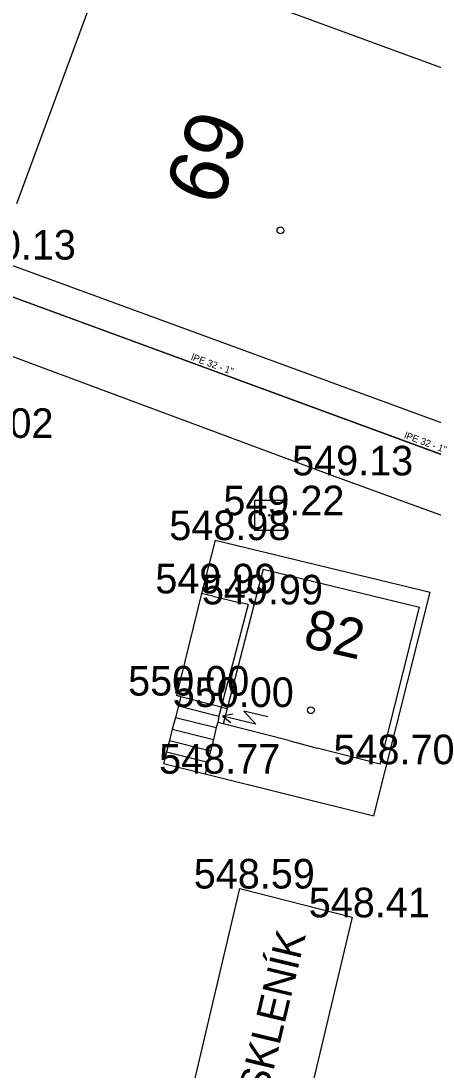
# Model space of a CAD drawing. Extents: x -669995 to -669686, y -1125551 to -1125263.
# Drawn here: x -669796.45 to -669786.01, y -1125325.67 to -1125299.08 of the extents above; entities that cross this region are included whole.
import ezdxf

# ---------------------------------------------------------------- set-up
doc = ezdxf.new("R2010")
doc.units = 0
for name, color, linetype in [('G_Bod_tecka', 7, 'Continuous'), ('G_Bod_vyska', 7, 'Continuous'), ('G_Budovy-znacky', 7, 'Continuous'), ('G_Budovy_Objekty', 7, 'Continuous'), ('G_Budovy_vstupy', 7, 'Continuous'), ('G_Cesty_Schody', 7, 'Continuous'), ('G_Cisla_jina', 7, 'Continuous'), ('G_Cisla_popisna', 7, 'Continuous'), ('G_Ploty', 7, 'Continuous'), ('G_Poznamky_odkaz', 7, 'Continuous'), ('G_Site-Rozvadece', 7, 'Continuous'), ('G_Site-Sachty_N', 7, 'Continuous'), ('G_Z_VODA_podz_kotovane', 7, 'Continuous'), ('Vrstva 25', 7, 'Continuous'), ('Vrstva 4', 7, 'Continuous')]:
    doc.layers.add(name, color=color, linetype=linetype)

msp = doc.modelspace()

# ---------------------------------------------------------------- linework, layer by layer
at = {"layer": 'G_Bod_tecka'}
for p, q in [((-669788.56, -1125310.6), (-669788.56, -1125310.6)), ((-669790.16, -1125311.61), (-669790.16, -1125311.61)), ((-669791.53, -1125312.24), (-669791.53, -1125312.24)), ((-669791.88, -1125313.59), (-669791.88, -1125313.59)), ((-669790.7, -1125313.87), (-669790.7, -1125313.87)), ((-669792.51, -1125316.18), (-669792.51, -1125316.18)), ((-669791.38, -1125316.47), (-669791.38, -1125316.47)), ((-669787.35, -1125317.92), (-669787.35, -1125317.92)), ((-669791.79, -1125318.16), (-669791.79, -1125318.16)), ((-669790.91, -1125321.07), (-669790.91, -1125321.07)), ((-669788.06, -1125321.8), (-669788.06, -1125321.8))]:
    msp.add_line(p, q, dxfattribs=at)
at = {"layer": 'G_Budovy-znacky'}
for centre in [(-669789.879, -1125304.39), (-669789.109, -1125316.551)]:
    msp.add_circle(centre, 0.0875, dxfattribs=at)
at = {"layer": 'G_Budovy_Objekty'}
for p, q in [((-669779.82, -1125302.48), (-669794.17, -1125297.19)), ((-669782.72, -1125310.4), (-669797.09, -1125305.13)), ((-669791.53, -1125312.24), (-669791.88, -1125313.59)), ((-669791.53, -1125312.24), (-669786.09, -1125313.56)), ((-669790.32, -1125312.98), (-669791.23, -1125316.51)), ((-669790.32, -1125312.98), (-669786.36, -1125313.94)), ((-669791.88, -1125313.59), (-669792.51, -1125316.18)), ((-669791.59, -1125313.66), (-669791.88, -1125313.59)), ((-669787.51, -1125319.23), (-669786.09, -1125313.56)), ((-669790.7, -1125313.87), (-669791.06, -1125315.26)), ((-669790.7, -1125313.87), (-669790.96, -1125313.81)), ((-669787.35, -1125317.92), (-669786.36, -1125313.94)), ((-669792.4, -1125316.21), (-669792.51, -1125316.18)), ((-669791.28, -1125316.08), (-669791.38, -1125316.47)), ((-669791.38, -1125316.47), (-669792.4, -1125316.21)), ((-669791.44, -1125316.7), (-669791.47, -1125316.86)), ((-669791.38, -1125316.47), (-669791.44, -1125316.7)), ((-669791.23, -1125316.51), (-669791.33, -1125316.9)), ((-669791.47, -1125316.86), (-669791.51, -1125316.99)), ((-669789.67, -1125317.32), (-669791.33, -1125316.9)), ((-669791.51, -1125316.99), (-669791.58, -1125317.29)), ((-669791.58, -1125317.29), (-669791.65, -1125317.58)), ((-669787.35, -1125317.92), (-669788.95, -1125317.51)), ((-669791.65, -1125317.58), (-669791.72, -1125317.87)), ((-669791.72, -1125317.87), (-669791.79, -1125318.16)), ((-669791.79, -1125318.16), (-669787.51, -1125319.23))]:
    msp.add_line(p, q, dxfattribs=at)
at = {"layer": 'G_Budovy_vstupy'}
for p, q in [((-669794.77, -1125298.84), (-669796.57, -1125303.72)), ((-669791.59, -1125313.66), (-669790.96, -1125313.81)), ((-669791.06, -1125315.26), (-669791.28, -1125316.08)), ((-669789.67, -1125317.32), (-669788.95, -1125317.51))]:
    msp.add_line(p, q, dxfattribs=at)
at = {"layer": 'G_Cesty_Schody'}
for p, q in [((-669792.46, -1125316.44), (-669792.54, -1125316.74)), ((-669792.4, -1125316.21), (-669792.46, -1125316.44)), ((-669792.46, -1125316.44), (-669791.44, -1125316.7)), ((-669792.54, -1125316.74), (-669792.62, -1125317.03)), ((-669792.54, -1125316.74), (-669791.51, -1125316.99)), ((-669792.62, -1125317.03), (-669792.69, -1125317.32)), ((-669792.62, -1125317.03), (-669791.58, -1125317.29)), ((-669792.69, -1125317.32), (-669792.77, -1125317.61)), ((-669792.69, -1125317.32), (-669791.65, -1125317.58)), ((-669792.77, -1125317.61), (-669792.84, -1125317.9)), ((-669792.77, -1125317.61), (-669791.72, -1125317.87)), ((-669792.84, -1125317.9), (-669791.79, -1125318.16)), ((-669792.29, -1125326.94), (-669790.91, -1125321.07)), ((-669790.91, -1125321.07), (-669788.06, -1125321.8)), ((-669788.06, -1125321.8), (-669789.45, -1125327.61))]:
    msp.add_line(p, q, dxfattribs=at)
at = {"layer": 'G_Ploty'}
for p, q in [((-669805, -1125304.49), (-669788.56, -1125310.6)), ((-669788.56, -1125310.6), (-669766.98, -1125318.52))]:
    msp.add_line(p, q, dxfattribs=at)
at = {"layer": 'G_Site-Rozvadece'}
for p, q in [((-669791.38, -1125316.47), (-669791.23, -1125316.51)), ((-669791.086, -1125316.651), (-669791.35, -1125316.7)), ((-669790.5, -1125316.907), (-669791.35, -1125316.7)), ((-669791.35, -1125316.7), (-669791.138, -1125316.865)), ((-669790.197, -1125316.723), (-669790.805, -1125316.575)), ((-669790.805, -1125316.575), (-669790.5, -1125316.907)), ((-669791.33, -1125316.9), (-669791.47, -1125316.86))]:
    msp.add_line(p, q, dxfattribs=at)
at = {"layer": 'G_Site-Sachty_N'}
msp.add_lwpolyline([(-669790.535, -1125311.985), (-669789.785, -1125311.985), (-669789.785, -1125311.235), (-669790.535, -1125311.235)], close=True, dxfattribs=at)
msp.add_circle((-669790.16, -1125311.61), 0.02, dxfattribs=at)
at = {"layer": 'G_Z_VODA_podz_kotovane'}
msp.add_lwpolyline([(-669804.76, -1125303.6), (-669797.34, -1125305.83), (-669784.7, -1125310.47), (-669784.44, -1125309.77)], dxfattribs=at)
at = {"layer": 'Vrstva 25'}
msp.add_lwpolyline([(-669804.757, -1125303.601), (-669797.345, -1125305.832), (-669784.7, -1125310.475), (-669784.441, -1125309.771)], dxfattribs=at)

# ---------------------------------------------------------------- texts
at = {"layer": 'G_Bod_vyska'}
for s, p in [('550.13', (-669798.131, -1125305.13)), ('549.02', (-669798.698, -1125309.65)), ('549.13', (-669789.584, -1125310.6)), ('549.22', (-669791.326, -1125311.61)), ('548.98', (-669792.696, -1125312.24)), ('549.99', (-669793.05, -1125313.59)), ('549.99', (-669791.87, -1125313.87)), ('550.00', (-669793.739, -1125316.18)), ('550.00', (-669792.609, -1125316.47)), ('548.70', (-669788.536, -1125317.92)), ('548.77', (-669792.954, -1125318.16)), ('548.59', (-669792.076, -1125321.07)), ('548.41', (-669789.162, -1125321.8))]:
    msp.add_text(s, height=0.75, dxfattribs=at).set_placement(p)
at = {"layer": 'G_Cisla_jina'}
msp.add_text('82', height=1, rotation=347.3275, dxfattribs=at).set_placement((-669789.336, -1125314.943))
at = {"layer": 'G_Cisla_popisna'}
msp.add_text('69', height=1.5, rotation=249.8159, dxfattribs=at).set_placement((-669792.069, -1125301.222))
at = {"layer": 'G_Poznamky_odkaz'}
msp.add_text('SKLENÍK', height=0.75, rotation=76.5453, dxfattribs=at).set_placement((-669790.218, -1125326.365))
at = {"layer": 'Vrstva 4'}
for rotation, p in [(339.9158, (-669792.159, -1125307.669)), (339.8906, (-669786.757, -1125309.652))]:
    msp.add_text('lPE 32 - 1"', height=0.17551, rotation=rotation, dxfattribs=at).set_placement(p)

doc.saveas('drawing.dxf')
